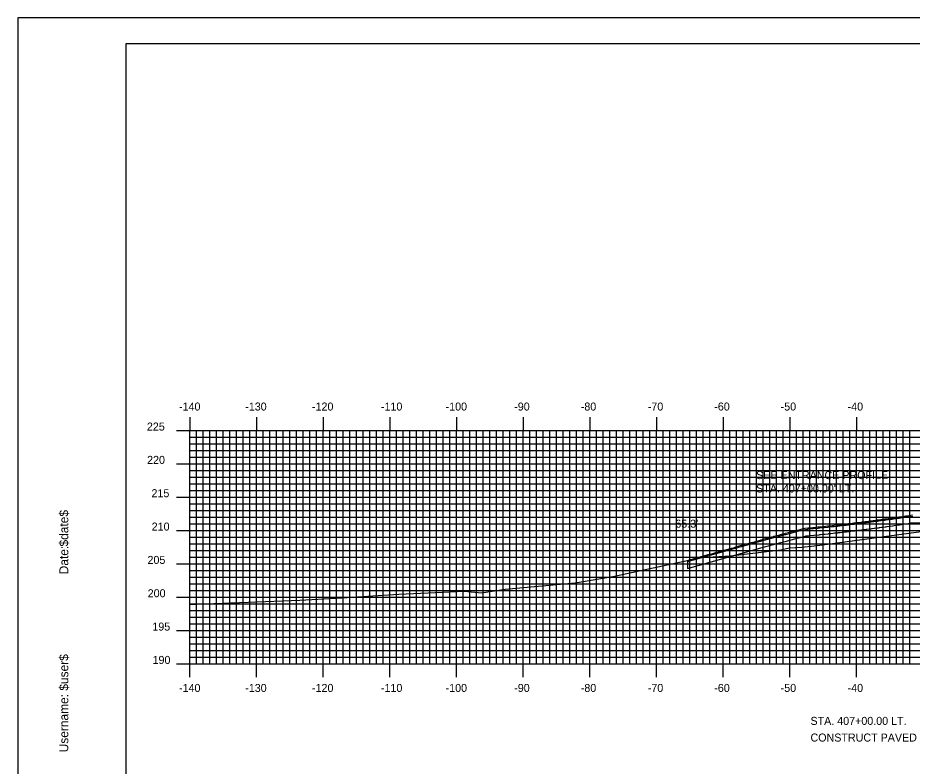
# Model space of a CAD drawing. Extents: x 852135 to 852479, y 364785 to 365005.
# Drawn here: x 852135.4 to 852269.5, y 364892.9 to 365005.1 of the extents above; entities that cross this region are included whole.
import ezdxf

# ---------------------------------------------------------------- set-up
doc = ezdxf.new("R2010")
doc.units = 0
for name, color, linetype in [('ANNOTATION', 7, 'Continuous'), ('BORDER', 7, 'Continuous'), ('D_Roadway_Centerline', 7, 'Continuous'), ('D_Roadway_Drive_Paved_LT', 7, 'Continuous'), ('D_Roadway_Drive_SubGrade', 7, 'Continuous'), ('D_Text_Standard', 7, 'Continuous'), ('H_V ANNOTATION', 7, 'Continuous'), ('MAJOR', 7, 'Continuous'), ('MINOR', 7, 'Continuous'), ('PLOT BOUNDARY', 7, 'Continuous'), ('S_Roadway_Centerline', 7, 'Continuous')]:
    doc.layers.add(name, color=color, linetype=linetype)

msp = doc.modelspace()

# ---------------------------------------------------------------- linework, layer by layer
at = {"layer": 'BORDER'}
msp.add_lwpolyline([(852151.62, 364791.23), (852471.62, 364791.23), (852471.62, 365001.23), (852151.62, 365001.23)], close=True, dxfattribs=at)
at = {"layer": 'D_Roadway_Centerline'}
msp.add_lwpolyline([(852235.88, 364923.76), (852236.17, 364923.84), (852236.2, 364923.85), (852236.87, 364924.04), (852237.46, 364924.2), (852237.56, 364924.23), (852238.12, 364924.39), (852238.26, 364924.43), (852238.79, 364924.57), (852238.95, 364924.62), (852239.45, 364924.76), (852239.65, 364924.81), (852240.11, 364924.94), (852240.34, 364925.01), (852240.62, 364925.08), (852241.04, 364925.2), (852241.37, 364925.29), (852241.73, 364925.4), (852242.12, 364925.5), (852242.43, 364925.59), (852242.88, 364925.71), (852243.12, 364925.78), (852243.62, 364925.92), (852243.82, 364925.98), (852244.37, 364926.13), (852244.51, 364926.17), (852245.11, 364926.34), (852245.21, 364926.37), (852245.85, 364926.54), (852245.9, 364926.56), (852246.59, 364926.75), (852246.6, 364926.75), (852246.74, 364926.79), (852247.24, 364926.93), (852247.29, 364926.95), (852247.36, 364926.97), (852247.99, 364927.14), (852248.5, 364927.29), (852248.68, 364927.34), (852248.75, 364927.36), (852248.78, 364927.37), (852249.25, 364927.49), (852249.53, 364927.56), (852249.95, 364927.67), (852250.41, 364927.79), (852250.49, 364927.81), (852250.55, 364927.83), (852251.02, 364927.95), (852251.29, 364928.02), (852251.54, 364928.08), (852252.17, 364928.24), (852252.3, 364928.28), (852252.33, 364928.29), (852252.44, 364928.31), (852253.05, 364928.47), (852253.46, 364928.58), (852253.89, 364928.62), (852253.89, 364928.62), (852254.05, 364928.63), (852254.08, 364928.64), (852254.67, 364928.69), (852254.75, 364928.7), (852255.42, 364928.77), (852255.45, 364928.77), (852255.58, 364928.78), (852255.69, 364928.8), (852256.16, 364928.84), (852256.33, 364928.86), (852256.87, 364928.92), (852256.92, 364928.92), (852257.04, 364928.94), (852257.21, 364928.96), (852257.57, 364928.99), (852257.81, 364929.02), (852258.25, 364929.07), (852258.32, 364929.08), (852258.42, 364929.09), (852258.63, 364929.12), (852258.91, 364929.14), (852259.22, 364929.18), (852259.56, 364929.22), (852259.65, 364929.23), (852259.74, 364929.24), (852259.98, 364929.27), (852260.2, 364929.29), (852260.55, 364929.34), (852260.82, 364929.37), (852260.93, 364929.38), (852261.01, 364929.39), (852261.27, 364929.43), (852261.43, 364929.44), (852261.83, 364929.5), (852262.03, 364929.52), (852262.16, 364929.54), (852262.22, 364929.54), (852262.5, 364929.58), (852262.62, 364929.59), (852263.05, 364929.65), (852263.2, 364929.67), (852263.35, 364929.69), (852263.4, 364929.69), (852263.69, 364929.73), (852263.77, 364929.74), (852264.22, 364929.81), (852264.34, 364929.82), (852264.5, 364929.84), (852264.54, 364929.85), (852264.83, 364929.89), (852264.89, 364929.89), (852265.36, 364929.96), (852265.44, 364929.97), (852265.62, 364929.99), (852265.65, 364930), (852265.94, 364930.04), (852265.98, 364930.04), (852266.46, 364930.11), (852266.52, 364930.12), (852266.71, 364930.15), (852266.73, 364930.15), (852267.02, 364930.19), (852267.05, 364930.19), (852267.53, 364930.26), (852267.57, 364930.27), (852267.78, 364930.3), (852267.79, 364930.3), (852268.08, 364930.34), (852268.09, 364930.34), (852268.59, 364930.42), (852268.61, 364930.42), (852268.83, 364930.45), (852268.84, 364930.45), (852269.11, 364930.49), (852269.12, 364930.49), (852269.62, 364930.57)], dxfattribs=at)
at = {"layer": 'D_Roadway_Drive_Paved_LT'}
msp.add_lwpolyline([(852235.88, 364923.59), (852246.78, 364926.63), (852248.82, 364927.21), (852249.58, 364927.4), (852250.45, 364927.63), (852250.59, 364927.66), (852251.33, 364927.86), (852252.21, 364928.08), (852252.37, 364928.12), (852253.09, 364928.31), (852253.49, 364928.41), (852253.91, 364928.45), (852253.91, 364928.45), (852254.06, 364928.47), (852254.1, 364928.47), (852254.68, 364928.53), (852254.77, 364928.54), (852255.44, 364928.6), (852255.47, 364928.61), (852255.6, 364928.62), (852255.71, 364928.63), (852256.17, 364928.68), (852256.35, 364928.7), (852256.89, 364928.75), (852256.94, 364928.76), (852257.06, 364928.77), (852257.22, 364928.79), (852257.59, 364928.83), (852257.83, 364928.86), (852258.27, 364928.9), (852258.34, 364928.91), (852258.44, 364928.92), (852258.65, 364928.95), (852258.93, 364928.98), (852259.24, 364929.02), (852259.58, 364929.05), (852259.67, 364929.06), (852259.76, 364929.07), (852260, 364929.11), (852260.22, 364929.13), (852260.57, 364929.18), (852260.84, 364929.2), (852260.95, 364929.22), (852261.03, 364929.23), (852261.29, 364929.26), (852261.45, 364929.28), (852261.85, 364929.33), (852262.05, 364929.35), (852262.18, 364929.37), (852262.24, 364929.38), (852262.52, 364929.42), (852262.64, 364929.43), (852263.07, 364929.49), (852263.22, 364929.5), (852263.37, 364929.52), (852263.42, 364929.53), (852263.71, 364929.57), (852263.79, 364929.58), (852264.24, 364929.64), (852264.36, 364929.65), (852264.52, 364929.68), (852264.56, 364929.68), (852264.85, 364929.72), (852264.91, 364929.73), (852265.38, 364929.79), (852265.46, 364929.8), (852265.64, 364929.83), (852265.67, 364929.83), (852265.96, 364929.87), (852266, 364929.88), (852266.48, 364929.95), (852266.54, 364929.95), (852266.73, 364929.98), (852266.75, 364929.98), (852267.04, 364930.03), (852267.07, 364930.03), (852267.55, 364930.1), (852267.59, 364930.1), (852267.8, 364930.13), (852267.81, 364930.13), (852268.1, 364930.18), (852268.11, 364930.18), (852268.61, 364930.25), (852268.63, 364930.25), (852268.85, 364930.29), (852268.86, 364930.29), (852269.13, 364930.33), (852269.14, 364930.33), (852269.64, 364930.4)], dxfattribs=at)
at = {"layer": 'D_Roadway_Drive_SubGrade'}
for p, q in [((852280.22, 364929.42), (852269.22, 364929.33)), ((852235.88, 364923.76), (852235.88, 364922.55))]:
    msp.add_line(p, q, dxfattribs=at)
msp.add_lwpolyline([(852235.88, 364922.55), (852247.05, 364925.67), (852249.09, 364926.24), (852249.83, 364926.43), (852250.7, 364926.66), (852250.84, 364926.7), (852251.58, 364926.89), (852252.46, 364927.12), (852252.62, 364927.16), (852253.34, 364927.34), (852253.66, 364927.43), (852254.01, 364927.46), (852254.02, 364927.46), (852254.17, 364927.47), (852254.2, 364927.48), (852254.79, 364927.53), (852254.87, 364927.54), (852255.55, 364927.61), (852255.58, 364927.61), (852255.71, 364927.63), (852255.82, 364927.64), (852256.28, 364927.68), (852256.46, 364927.71), (852257, 364927.76), (852257.05, 364927.77), (852257.17, 364927.78), (852257.34, 364927.8), (852257.7, 364927.83), (852257.95, 364927.87), (852258.38, 364927.91), (852258.45, 364927.92), (852258.56, 364927.93), (852258.77, 364927.96), (852259.05, 364927.98), (852259.35, 364928.02), (852259.7, 364928.06), (852259.79, 364928.07), (852259.88, 364928.08), (852260.12, 364928.11), (852260.33, 364928.13), (852260.69, 364928.18), (852260.96, 364928.21), (852261.07, 364928.22), (852261.14, 364928.23), (852261.41, 364928.27), (852261.57, 364928.28), (852261.97, 364928.34), (852262.17, 364928.36), (852262.3, 364928.38), (852262.36, 364928.38), (852262.64, 364928.42), (852262.76, 364928.43), (852263.19, 364928.49), (852263.34, 364928.51), (852263.49, 364928.53), (852263.54, 364928.54), (852263.83, 364928.58), (852263.91, 364928.59), (852264.36, 364928.65), (852264.48, 364928.66), (852264.64, 364928.68), (852264.68, 364928.69), (852264.97, 364928.73), (852265.03, 364928.74), (852265.5, 364928.8), (852265.58, 364928.81), (852265.76, 364928.84), (852265.79, 364928.84), (852266.08, 364928.88), (852266.12, 364928.89), (852266.6, 364928.95), (852266.66, 364928.96), (852266.85, 364928.99), (852266.87, 364928.99), (852267.16, 364929.03), (852267.19, 364929.04), (852267.68, 364929.11), (852267.71, 364929.11), (852267.92, 364929.14), (852267.94, 364929.14), (852268.22, 364929.18), (852268.23, 364929.19), (852268.73, 364929.26), (852268.75, 364929.26), (852268.97, 364929.29), (852268.98, 364929.29), (852269.22, 364929.33)], dxfattribs=at)
at = {"layer": 'MAJOR'}
for p, q in [((852161.22, 364945.24), (852161.22, 364943.23)), ((852171.22, 364945.24), (852171.22, 364943.23)), ((852181.22, 364945.24), (852181.22, 364943.23)), ((852191.22, 364945.24), (852191.22, 364943.23)), ((852201.22, 364945.24), (852201.22, 364943.23)), ((852211.22, 364945.24), (852211.22, 364943.23)), ((852221.22, 364945.24), (852221.22, 364943.23)), ((852231.22, 364945.24), (852231.22, 364943.23)), ((852241.22, 364945.24), (852241.22, 364943.23)), ((852251.22, 364945.24), (852251.22, 364943.23)), ((852261.22, 364945.24), (852261.22, 364943.23)), ((852159.21, 364943.23), (852161.22, 364943.23)), ((852161.22, 364943.23), (852441.22, 364943.23)), ((852161.22, 364908.23), (852161.22, 364943.23)), ((852161.22, 364908.23), (852161.22, 364943.23)), ((852161.22, 364943.23), (852441.22, 364943.23)), ((852171.22, 364908.23), (852171.22, 364943.23)), ((852181.22, 364908.23), (852181.22, 364943.23)), ((852191.22, 364908.23), (852191.22, 364943.23)), ((852201.22, 364908.23), (852201.22, 364943.23)), ((852211.22, 364908.23), (852211.22, 364943.23)), ((852221.22, 364908.23), (852221.22, 364943.23)), ((852231.22, 364908.23), (852231.22, 364943.23)), ((852241.22, 364908.23), (852241.22, 364943.23)), ((852251.22, 364908.23), (852251.22, 364943.23)), ((852261.22, 364908.23), (852261.22, 364943.23)), ((852159.21, 364938.23), (852161.22, 364938.23)), ((852161.22, 364938.23), (852441.22, 364938.23)), ((852159.21, 364933.23), (852161.22, 364933.23)), ((852161.22, 364933.23), (852441.22, 364933.23)), ((852159.21, 364928.23), (852161.22, 364928.23)), ((852161.22, 364928.23), (852441.22, 364928.23)), ((852159.21, 364923.23), (852161.22, 364923.23)), ((852161.22, 364923.23), (852441.22, 364923.23)), ((852159.21, 364918.23), (852161.22, 364918.23)), ((852161.22, 364918.23), (852441.22, 364918.23)), ((852159.21, 364913.23), (852161.22, 364913.23)), ((852161.22, 364913.23), (852441.22, 364913.23)), ((852159.21, 364908.23), (852161.22, 364908.23)), ((852161.22, 364908.23), (852441.22, 364908.23)), ((852161.22, 364908.23), (852441.22, 364908.23)), ((852161.22, 364906.23), (852161.22, 364908.23)), ((852171.22, 364906.23), (852171.22, 364908.23)), ((852181.22, 364906.23), (852181.22, 364908.23)), ((852191.22, 364906.23), (852191.22, 364908.23)), ((852201.22, 364906.23), (852201.22, 364908.23)), ((852211.22, 364906.23), (852211.22, 364908.23)), ((852221.22, 364906.23), (852221.22, 364908.23)), ((852231.22, 364906.23), (852231.22, 364908.23)), ((852241.22, 364906.23), (852241.22, 364908.23)), ((852251.22, 364906.23), (852251.22, 364908.23)), ((852261.22, 364906.23), (852261.22, 364908.23))]:
    msp.add_line(p, q, dxfattribs=at)
at = {"layer": 'MINOR'}
for p, q in [((852162.22, 364908.23), (852162.22, 364943.23)), ((852163.22, 364908.23), (852163.22, 364943.23)), ((852164.22, 364908.23), (852164.22, 364943.23)), ((852165.22, 364908.23), (852165.22, 364943.23)), ((852166.22, 364908.23), (852166.22, 364943.23)), ((852167.22, 364908.23), (852167.22, 364943.23)), ((852168.22, 364908.23), (852168.22, 364943.23)), ((852169.22, 364908.23), (852169.22, 364943.23)), ((852170.22, 364908.23), (852170.22, 364943.23)), ((852172.22, 364908.23), (852172.22, 364943.23)), ((852173.22, 364908.23), (852173.22, 364943.23)), ((852174.22, 364908.23), (852174.22, 364943.23)), ((852175.22, 364908.23), (852175.22, 364943.23)), ((852176.22, 364908.23), (852176.22, 364943.23)), ((852177.22, 364908.23), (852177.22, 364943.23)), ((852178.22, 364908.23), (852178.22, 364943.23)), ((852179.22, 364908.23), (852179.22, 364943.23)), ((852180.22, 364908.23), (852180.22, 364943.23)), ((852182.22, 364908.23), (852182.22, 364943.23)), ((852183.22, 364908.23), (852183.22, 364943.23)), ((852184.22, 364908.23), (852184.22, 364943.23)), ((852185.22, 364908.23), (852185.22, 364943.23)), ((852186.22, 364908.23), (852186.22, 364943.23)), ((852187.22, 364908.23), (852187.22, 364943.23)), ((852188.22, 364908.23), (852188.22, 364943.23)), ((852189.22, 364908.23), (852189.22, 364943.23)), ((852190.22, 364908.23), (852190.22, 364943.23)), ((852192.22, 364908.23), (852192.22, 364943.23)), ((852193.22, 364908.23), (852193.22, 364943.23)), ((852194.22, 364908.23), (852194.22, 364943.23)), ((852195.22, 364908.23), (852195.22, 364943.23)), ((852196.22, 364908.23), (852196.22, 364943.23)), ((852197.22, 364908.23), (852197.22, 364943.23)), ((852198.22, 364908.23), (852198.22, 364943.23)), ((852199.22, 364908.23), (852199.22, 364943.23)), ((852200.22, 364908.23), (852200.22, 364943.23)), ((852202.22, 364908.23), (852202.22, 364943.23)), ((852203.22, 364908.23), (852203.22, 364943.23)), ((852204.22, 364908.23), (852204.22, 364943.23)), ((852205.22, 364908.23), (852205.22, 364943.23)), ((852206.22, 364908.23), (852206.22, 364943.23)), ((852207.22, 364908.23), (852207.22, 364943.23)), ((852208.22, 364908.23), (852208.22, 364943.23)), ((852209.22, 364908.23), (852209.22, 364943.23)), ((852210.22, 364908.23), (852210.22, 364943.23)), ((852212.22, 364908.23), (852212.22, 364943.23)), ((852213.22, 364908.23), (852213.22, 364943.23)), ((852214.22, 364908.23), (852214.22, 364943.23)), ((852215.22, 364908.23), (852215.22, 364943.23)), ((852216.22, 364908.23), (852216.22, 364943.23)), ((852217.22, 364908.23), (852217.22, 364943.23)), ((852218.22, 364908.23), (852218.22, 364943.23)), ((852219.22, 364908.23), (852219.22, 364943.23)), ((852220.22, 364908.23), (852220.22, 364943.23)), ((852222.22, 364908.23), (852222.22, 364943.23)), ((852223.22, 364908.23), (852223.22, 364943.23)), ((852224.22, 364908.23), (852224.22, 364943.23)), ((852225.22, 364908.23), (852225.22, 364943.23)), ((852226.22, 364908.23), (852226.22, 364943.23)), ((852227.22, 364908.23), (852227.22, 364943.23)), ((852228.22, 364908.23), (852228.22, 364943.23)), ((852229.22, 364908.23), (852229.22, 364943.23)), ((852230.22, 364908.23), (852230.22, 364943.23)), ((852232.22, 364908.23), (852232.22, 364943.23)), ((852233.22, 364908.23), (852233.22, 364943.23)), ((852234.22, 364908.23), (852234.22, 364943.23)), ((852235.22, 364908.23), (852235.22, 364943.23)), ((852236.22, 364908.23), (852236.22, 364943.23)), ((852237.22, 364908.23), (852237.22, 364943.23)), ((852238.22, 364908.23), (852238.22, 364943.23)), ((852239.22, 364908.23), (852239.22, 364943.23)), ((852240.22, 364908.23), (852240.22, 364943.23)), ((852242.22, 364908.23), (852242.22, 364943.23)), ((852243.22, 364908.23), (852243.22, 364943.23)), ((852244.22, 364908.23), (852244.22, 364943.23)), ((852245.22, 364908.23), (852245.22, 364943.23)), ((852246.22, 364908.23), (852246.22, 364943.23)), ((852247.22, 364908.23), (852247.22, 364943.23)), ((852248.22, 364908.23), (852248.22, 364943.23)), ((852249.22, 364908.23), (852249.22, 364943.23)), ((852250.22, 364908.23), (852250.22, 364943.23)), ((852252.22, 364908.23), (852252.22, 364943.23)), ((852253.22, 364908.23), (852253.22, 364943.23)), ((852254.22, 364908.23), (852254.22, 364943.23)), ((852255.22, 364908.23), (852255.22, 364943.23)), ((852256.22, 364908.23), (852256.22, 364943.23)), ((852257.22, 364908.23), (852257.22, 364943.23)), ((852258.22, 364908.23), (852258.22, 364943.23)), ((852259.22, 364908.23), (852259.22, 364943.23)), ((852260.22, 364908.23), (852260.22, 364943.23)), ((852262.22, 364908.23), (852262.22, 364943.23)), ((852263.22, 364908.23), (852263.22, 364943.23)), ((852264.22, 364908.23), (852264.22, 364943.23)), ((852265.22, 364908.23), (852265.22, 364943.23)), ((852266.22, 364908.23), (852266.22, 364943.23)), ((852267.22, 364908.23), (852267.22, 364943.23)), ((852268.22, 364908.23), (852268.22, 364943.23)), ((852269.22, 364908.23), (852269.22, 364943.23)), ((852161.22, 364942.23), (852441.22, 364942.23)), ((852161.22, 364942.23), (852163.22, 364942.23)), ((852161.22, 364941.23), (852441.22, 364941.23)), ((852161.22, 364941.23), (852163.22, 364941.23)), ((852161.22, 364940.23), (852441.22, 364940.23)), ((852161.22, 364940.23), (852163.22, 364940.23)), ((852161.22, 364939.23), (852441.22, 364939.23)), ((852161.22, 364939.23), (852163.22, 364939.23)), ((852161.22, 364937.23), (852441.22, 364937.23)), ((852161.22, 364937.23), (852163.22, 364937.23)), ((852161.22, 364936.23), (852441.22, 364936.23)), ((852161.22, 364936.23), (852163.22, 364936.23)), ((852161.22, 364935.23), (852441.22, 364935.23)), ((852161.22, 364935.23), (852163.22, 364935.23)), ((852161.22, 364934.23), (852441.22, 364934.23)), ((852161.22, 364934.23), (852163.22, 364934.23)), ((852161.22, 364932.23), (852441.22, 364932.23)), ((852161.22, 364932.23), (852163.22, 364932.23)), ((852161.22, 364931.23), (852441.22, 364931.23)), ((852161.22, 364931.23), (852163.22, 364931.23)), ((852161.22, 364930.23), (852441.22, 364930.23)), ((852161.22, 364930.23), (852163.22, 364930.23)), ((852161.22, 364929.23), (852441.22, 364929.23)), ((852161.22, 364929.23), (852163.22, 364929.23)), ((852161.22, 364927.23), (852441.22, 364927.23)), ((852161.22, 364927.23), (852163.22, 364927.23)), ((852161.22, 364926.23), (852441.22, 364926.23)), ((852161.22, 364926.23), (852163.22, 364926.23)), ((852161.22, 364925.23), (852441.22, 364925.23)), ((852161.22, 364925.23), (852163.22, 364925.23)), ((852161.22, 364924.23), (852441.22, 364924.23)), ((852161.22, 364924.23), (852163.22, 364924.23)), ((852161.22, 364922.23), (852441.22, 364922.23)), ((852161.22, 364922.23), (852163.22, 364922.23)), ((852161.22, 364921.23), (852441.22, 364921.23)), ((852161.22, 364921.23), (852163.22, 364921.23)), ((852161.22, 364920.23), (852441.22, 364920.23)), ((852161.22, 364920.23), (852163.22, 364920.23)), ((852161.22, 364919.23), (852441.22, 364919.23)), ((852161.22, 364919.23), (852163.22, 364919.23)), ((852161.22, 364917.23), (852441.22, 364917.23)), ((852161.22, 364917.23), (852163.22, 364917.23)), ((852161.22, 364916.23), (852441.22, 364916.23)), ((852161.22, 364916.23), (852163.22, 364916.23)), ((852161.22, 364915.23), (852441.22, 364915.23)), ((852161.22, 364915.23), (852163.22, 364915.23)), ((852161.22, 364914.23), (852441.22, 364914.23)), ((852161.22, 364914.23), (852163.22, 364914.23)), ((852161.22, 364912.23), (852441.22, 364912.23)), ((852161.22, 364912.23), (852163.22, 364912.23)), ((852161.22, 364911.23), (852441.22, 364911.23)), ((852161.22, 364911.23), (852163.22, 364911.23)), ((852161.22, 364910.23), (852441.22, 364910.23)), ((852161.22, 364910.23), (852163.22, 364910.23)), ((852161.22, 364909.23), (852441.22, 364909.23)), ((852161.22, 364909.23), (852163.22, 364909.23))]:
    msp.add_line(p, q, dxfattribs=at)
at = {"layer": 'PLOT BOUNDARY'}
msp.add_lwpolyline([(852135.43, 364785.11), (852475.43, 364785.11), (852475.43, 365005.11), (852135.43, 365005.11)], close=True, dxfattribs=at)
at = {"layer": 'S_Roadway_Centerline'}
msp.add_lwpolyline([(852161.22, 364917.13), (852162.21, 364917.2), (852177.72, 364917.8), (852183.99, 364918.15), (852192.58, 364918.68), (852202.41, 364919.16), (852204.98, 364918.89), (852208.51, 364919.43), (852219.02, 364920.4), (852224.66, 364921.32), (852237.44, 364924.1), (852237.97, 364924.23), (852238, 364924.21), (852242.32, 364924.44), (852249.86, 364925.33), (852251.12, 364925.66), (852253.01, 364925.75), (852253.39, 364925.77), (852254.47, 364925.88), (852255.7, 364926.04), (852256.11, 364926.11), (852270.92, 364928.07)], dxfattribs=at)

# ---------------------------------------------------------------- texts
at = {"layer": 'ANNOTATION'}
for s, p in [('SEE ENTRANCE PROFILE', (852246.15, 364935.95)), ("STA. 407+00.00' LT.", (852246.15, 364933.94))]:
    msp.add_text(s, height=1.2, dxfattribs=at).set_placement(p)
at = {"layer": 'BORDER'}
for s, p in [('$date$', (852142.99, 364925.84)), ('Date:', (852142.99, 364921.67)), ('$user$', (852142.99, 364904.22)), ('Username:', (852142.99, 364894.97))]:
    msp.add_text(s, height=1.339, rotation=90, dxfattribs=at).set_placement(p)
at = {"layer": 'D_Text_Standard'}
for s, p in [("65.3'", (852234.03, 364928.67)), ('STA. 407+00.00 LT.', (852254.3, 364899.09)), ('CONSTRUCT PAVED ENTRANCE', (852254.3, 364896.59))]:
    msp.add_text(s, height=1.2, dxfattribs=at).set_placement(p)
at = {"layer": 'H_V ANNOTATION'}
for s, p in [('-140', (852159.6, 364946.23)), ('-130', (852169.53, 364946.23)), ('-120', (852179.54, 364946.23)), ('-110', (852189.88, 364946.23)), ('-100', (852199.58, 364946.23)), ('-90', (852209.87, 364946.23)), ('-80', (852219.85, 364946.23)), ('-70', (852229.9, 364946.23)), ('-60', (852239.87, 364946.23)), ('-50', (852249.83, 364946.23)), ('-40', (852259.87, 364946.23)), ('225', (852154.78, 364943.23)), ('220', (852154.81, 364938.23)), ('215', (852155.47, 364933.23)), ('210', (852155.5, 364928.23)), ('205', (852154.87, 364923.23)), ('200', (852154.9, 364918.23)), ('195', (852155.6, 364913.23)), ('190', (852155.63, 364908.23)), ('-140', (852159.6, 364904.03)), ('-130', (852169.53, 364904.03)), ('-120', (852179.54, 364904.03)), ('-110', (852189.88, 364904.03)), ('-100', (852199.58, 364904.03)), ('-90', (852209.87, 364904.03)), ('-80', (852219.85, 364904.03)), ('-70', (852229.9, 364904.03)), ('-60', (852239.87, 364904.03)), ('-50', (852249.83, 364904.03)), ('-40', (852259.87, 364904.03))]:
    msp.add_text(s, height=1.2, dxfattribs=at).set_placement(p)
at = {"layer": 'MAJOR'}
msp.add_text('-', height=0.012, dxfattribs=at).set_placement((852161.21, 364908.23))

doc.saveas('drawing.dxf')
